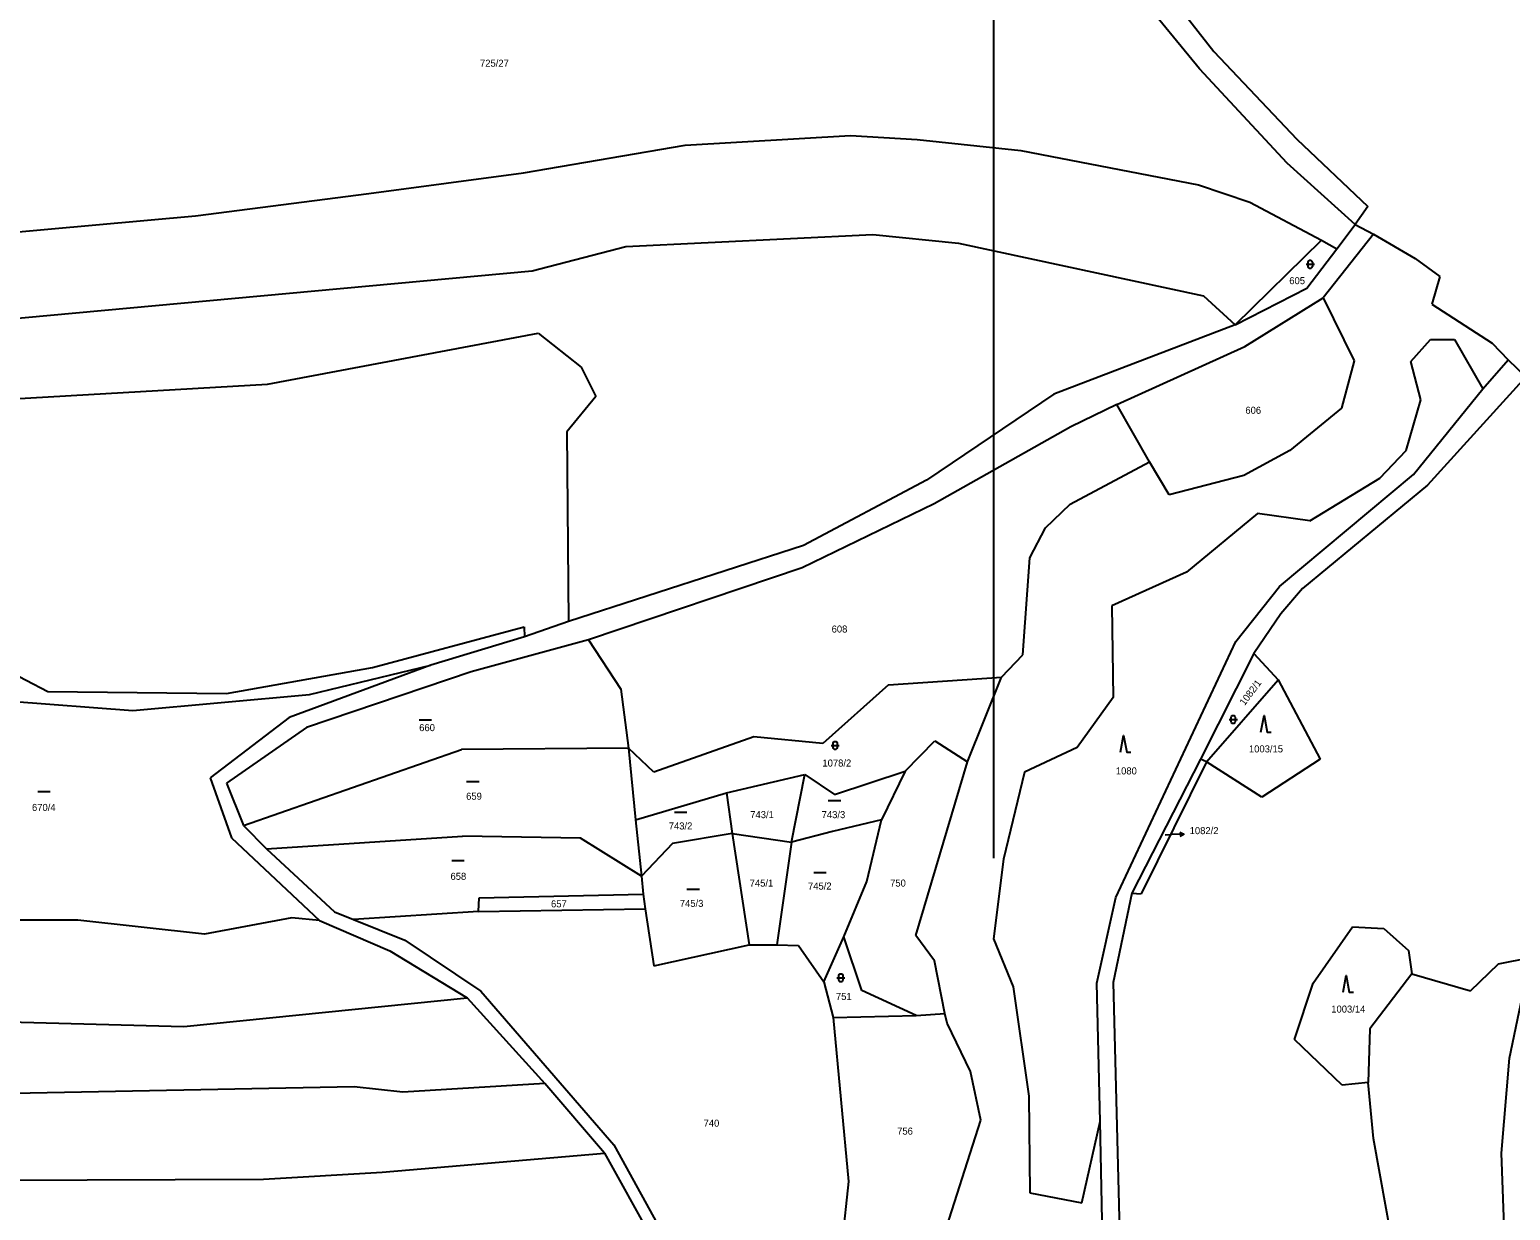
# Model space of a CAD drawing. Extents: x -799786 to -795190, y -1021716 to -1017834.
# Drawn here: x -798982.6 to -798625.3, y -1019585 to -1019300.1 of the extents above; entities that cross this region are included whole.
import ezdxf

# ---------------------------------------------------------------- set-up
doc = ezdxf.new("R2010")
doc.units = 0
for name, color, linetype in [('Default', 7, 'Continuous'), ('KLADY_ZMVM', 7, 'Continuous'), ('KN_HRANICE', 7, 'Continuous'), ('KN_KULTURY', 7, 'Continuous'), ('KN_PARCELY', 7, 'Continuous')]:
    doc.layers.add(name, color=color, linetype=linetype)

# ---------------------------------------------------------------- blocks, each defined once
blk = doc.blocks.new('308')
at = {"layer": 'Default'}
blk.add_lwpolyline([(-0.75, 0), (0, 4), (0.75, 0), (1.75, 0)], dxfattribs=at)
blk = doc.blocks.new('316')
at = {"layer": 'Default'}
for points in [[(-1, 1), (0.27, 1), (1, 1)], [(-0.5, 1.5), (-0.4, 1.79), (-0.15, 1.97), (0.16, 1.97), (0.41, 1.79), (0.51, 1.5), (0.51, 0.5), (0.41, 0.21), (0.16, 0.03), (-0.15, 0.03), (-0.4, 0.21), (-0.5, 0.5), (-0.5, 1.5)]]:
    blk.add_lwpolyline(points, dxfattribs=at)
blk = doc.blocks.new('804')
at = {"layer": 'Default'}
blk.add_line((-1.5, 0), (1.5, 0), dxfattribs=at)
blk = doc.blocks.new('10292')
at = {"layer": 'Default'}
blk.add_line((0, 3), (0, 0), dxfattribs=at)
blk.add_lwpolyline([(-0.5, 2), (0, 3), (0.5, 2)], dxfattribs=at)

msp = doc.modelspace()

# ---------------------------------------------------------------- linework, layer by layer
at = {"layer": 'KLADY_ZMVM'}
msp.add_lwpolyline([(-798750, -1018500), (-798750, -1019000), (-798750, -1019500)], dxfattribs=at)
at = {"layer": 'KN_HRANICE'}
for p, q in [((-798712.66, -1019285.13), (-798696.86, -1019305.37)), ((-798700.33, -1019309.58), (-798717.83, -1019288.18)), ((-798696.86, -1019305.37), (-798676.85, -1019326.52)), ((-798679.17, -1019332.32), (-798700.33, -1019309.58)), ((-798824.38, -1019327.98), (-798784.49, -1019325.66)), ((-798784.49, -1019325.66), (-798768.48, -1019326.61)), ((-798768.48, -1019326.61), (-798743.43, -1019329.24)), ((-798676.85, -1019326.52), (-798659.76, -1019342.78)), ((-798863.37, -1019334.62), (-798824.38, -1019327.98)), ((-798743.43, -1019329.24), (-798700.56, -1019337.56)), ((-798662.82, -1019347.1), (-798679.17, -1019332.32)), ((-798900.7, -1019339.67), (-798863.37, -1019334.62)), ((-798700.56, -1019337.56), (-798688.21, -1019341.73)), ((-798942.54, -1019345.04), (-798900.7, -1019339.67)), ((-799021.28, -1019352.13), (-798942.54, -1019345.04)), ((-798688.21, -1019341.73), (-798670.93, -1019350.9)), ((-798659.76, -1019342.78), (-798662.82, -1019347.1)), ((-798667.24, -1019353.01), (-798662.82, -1019347.1)), ((-798662.82, -1019347.1), (-798658.39, -1019349.42)), ((-798838.7, -1019352.43), (-798779.12, -1019349.49)), ((-798779.12, -1019349.49), (-798758.47, -1019351.59)), ((-798758.47, -1019351.59), (-798699.41, -1019364.34)), ((-798691.75, -1019371.31), (-798670.93, -1019350.9)), ((-798670.93, -1019350.9), (-798667.24, -1019353.01)), ((-798658.39, -1019349.42), (-798670.51, -1019364.81)), ((-798658.39, -1019349.42), (-798648.3, -1019355.31)), ((-798861.35, -1019358.33), (-798838.7, -1019352.43)), ((-798674.41, -1019362.49), (-798667.24, -1019353.01)), ((-798648.3, -1019355.31), (-798642.4, -1019359.63)), ((-798900.6, -1019361.91), (-798861.35, -1019358.33)), ((-799007.83, -1019371.82), (-798900.6, -1019361.91)), ((-798691.75, -1019371.31), (-798674.41, -1019362.49)), ((-798642.4, -1019359.63), (-798644.3, -1019366.37)), ((-798699.41, -1019364.34), (-798691.75, -1019371.31)), ((-798689.42, -1019376.56), (-798670.51, -1019364.81)), ((-798670.51, -1019364.81), (-798663.02, -1019379.97)), ((-798644.3, -1019366.37), (-798629.75, -1019375.76)), ((-798925.2, -1019385.65), (-798859.9, -1019373.32)), ((-798859.9, -1019373.32), (-798849.47, -1019381.55)), ((-798691.75, -1019371.31), (-798735.45, -1019388.04)), ((-798720.28, -1019390.57), (-798689.42, -1019376.56)), ((-798649.35, -1019380.16), (-798644.61, -1019374.89)), ((-798644.61, -1019374.89), (-798638.81, -1019374.89)), ((-798638.81, -1019374.89), (-798631.96, -1019386.8)), ((-798629.75, -1019375.76), (-798625.85, -1019379.76)), ((-798663.02, -1019379.97), (-798666.08, -1019391.46)), ((-798646.92, -1019389.44), (-798649.35, -1019380.16)), ((-798631.96, -1019386.8), (-798625.85, -1019379.76)), ((-798625.85, -1019379.76), (-798621.64, -1019383.87)), ((-798849.47, -1019381.55), (-798845.99, -1019388.61)), ((-798621.64, -1019383.87), (-798645.34, -1019409.99)), ((-799017.43, -1019390.93), (-798925.2, -1019385.65)), ((-798735.45, -1019388.04), (-798766.21, -1019408.79)), ((-798648.72, -1019407.46), (-798631.96, -1019386.8)), ((-798845.99, -1019388.61), (-798852.95, -1019397.15)), ((-798720.28, -1019390.57), (-798731.34, -1019395.94)), ((-798712.41, -1019404.41), (-798720.28, -1019390.57)), ((-798666.08, -1019391.46), (-798678.58, -1019401.67)), ((-798650.51, -1019401.66), (-798646.92, -1019389.44)), ((-798852.95, -1019397.15), (-798852.53, -1019442.89)), ((-798731.34, -1019395.94), (-798764.32, -1019414.49)), ((-798678.58, -1019401.67), (-798689.65, -1019407.68)), ((-798656.83, -1019408.3), (-798650.51, -1019401.66)), ((-798731.57, -1019414.61), (-798712.41, -1019404.41)), ((-798707.67, -1019412.32), (-798712.41, -1019404.41)), ((-798766.21, -1019408.79), (-798795.9, -1019424.57)), ((-798689.65, -1019407.68), (-798707.67, -1019412.32)), ((-798681.05, -1019434.41), (-798648.72, -1019407.46)), ((-798673.69, -1019418.64), (-798656.83, -1019408.3)), ((-798645.34, -1019409.99), (-798675.46, -1019434.93)), ((-798764.32, -1019414.49), (-798796.21, -1019429.95)), ((-798737.47, -1019420.31), (-798731.57, -1019414.61)), ((-798686.33, -1019416.84), (-798703.49, -1019431.03)), ((-798673.69, -1019418.64), (-798686.33, -1019416.84)), ((-798741.25, -1019427.55), (-798737.47, -1019420.31)), ((-798795.9, -1019424.57), (-798852.53, -1019442.89)), ((-798796.21, -1019429.95), (-798847.69, -1019447.32)), ((-798742.93, -1019450.95), (-798741.25, -1019427.55)), ((-798703.49, -1019431.03), (-798721.51, -1019439.15)), ((-798691.58, -1019447.69), (-798681.05, -1019434.41)), ((-798675.46, -1019434.93), (-798680.73, -1019441.05)), ((-798721.51, -1019439.15), (-798721.17, -1019461.24)), ((-798680.73, -1019441.05), (-798687.26, -1019450.64)), ((-798899.85, -1019453.96), (-798863.28, -1019444.15)), ((-798863.28, -1019444.15), (-798863.18, -1019446.58)), ((-798852.53, -1019442.89), (-798863.18, -1019446.58)), ((-798863.18, -1019446.58), (-798885.73, -1019453.43)), ((-798847.69, -1019447.32), (-798876.03, -1019455.01)), ((-798847.69, -1019447.32), (-798839.89, -1019459.23)), ((-798720.54, -1019509.52), (-798691.58, -1019447.69)), ((-798748.1, -1019456.33), (-798742.93, -1019450.95)), ((-798687.26, -1019450.64), (-798700.1, -1019476.1)), ((-798687.26, -1019450.64), (-798681.36, -1019456.97)), ((-798988.61, -1019454.34), (-798978.18, -1019459.77)), ((-798935.07, -1019460.27), (-798899.85, -1019453.96)), ((-798885.73, -1019453.43), (-798919.97, -1019466.08)), ((-798876.03, -1019455.01), (-798915.74, -1019468.48)), ((-798915.02, -1019460.49), (-798885.73, -1019453.43)), ((-798839.89, -1019459.23), (-798838.1, -1019473.46)), ((-798775.39, -1019458.21), (-798791.19, -1019472.31)), ((-798775.39, -1019458.21), (-798748.1, -1019456.33)), ((-798756.31, -1019476.73), (-798748.1, -1019456.33)), ((-798698.62, -1019476.74), (-798681.36, -1019456.97)), ((-798681.36, -1019456.97), (-798671.22, -1019476.1)), ((-798987.14, -1019462.09), (-798957.62, -1019464.38)), ((-798978.18, -1019459.77), (-798935.07, -1019460.27)), ((-798957.62, -1019464.38), (-798915.02, -1019460.49)), ((-798721.17, -1019461.24), (-798729.81, -1019473.26)), ((-798919.97, -1019466.08), (-798939.03, -1019480.6)), ((-798915.74, -1019468.48), (-798935.03, -1019481.86)), ((-798930.92, -1019492.09), (-798878.34, -1019473.75)), ((-798838.1, -1019473.46), (-798878.34, -1019473.75)), ((-798838.1, -1019473.46), (-798836.41, -1019490.72)), ((-798831.96, -1019479.28), (-798838.1, -1019473.46)), ((-798807.84, -1019470.72), (-798831.96, -1019479.28)), ((-798791.19, -1019472.31), (-798807.84, -1019470.72)), ((-798771.38, -1019479.04), (-798764.22, -1019471.67)), ((-798764.22, -1019471.67), (-798756.31, -1019476.73)), ((-798729.81, -1019473.26), (-798742.56, -1019479.27)), ((-798768.76, -1019518.63), (-798756.31, -1019476.73)), ((-798700.1, -1019476.1), (-798716.64, -1019508.47)), ((-798698.62, -1019476.74), (-798714.43, -1019508.57)), ((-798698.62, -1019476.74), (-798700.1, -1019476.1)), ((-798685.34, -1019485.27), (-798698.62, -1019476.74)), ((-798671.22, -1019476.1), (-798685.34, -1019485.27)), ((-798939.03, -1019480.6), (-798933.88, -1019495.07)), ((-798814.48, -1019484.22), (-798795.51, -1019479.79)), ((-798798.78, -1019496.11), (-798795.51, -1019479.79)), ((-798795.51, -1019479.79), (-798788.35, -1019484.62)), ((-798788.35, -1019484.62), (-798771.38, -1019479.04)), ((-798771.38, -1019479.04), (-798777.07, -1019490.74)), ((-798742.56, -1019479.27), (-798747.62, -1019500.24)), ((-798935.03, -1019481.86), (-798930.92, -1019492.09)), ((-798836.41, -1019490.72), (-798814.48, -1019484.22)), ((-798814.48, -1019484.22), (-798813.11, -1019494.02)), ((-798836.41, -1019490.72), (-798834.94, -1019504.32)), ((-798777.07, -1019490.74), (-798788.88, -1019493.58)), ((-798780.55, -1019505.6), (-798777.07, -1019490.74)), ((-798933.88, -1019495.07), (-798912.6, -1019515.04)), ((-798930.92, -1019492.09), (-798925.44, -1019497.78)), ((-798925.44, -1019497.78), (-798878.13, -1019494.72)), ((-798849.67, -1019495.15), (-798878.13, -1019494.72)), ((-798834.94, -1019504.32), (-798849.67, -1019495.15)), ((-798813.11, -1019494.02), (-798827.44, -1019496.45)), ((-798813.11, -1019494.02), (-798809, -1019520.89)), ((-798813.11, -1019494.02), (-798798.78, -1019496.11)), ((-798788.88, -1019493.58), (-798798.78, -1019496.11)), ((-798925.44, -1019497.78), (-798909.01, -1019512.93)), ((-798827.44, -1019496.45), (-798834.94, -1019504.32)), ((-798798.78, -1019496.11), (-798802.26, -1019520.89)), ((-798747.62, -1019500.24), (-798750, -1019519.48)), ((-798834.94, -1019504.32), (-798834.52, -1019508.65)), ((-798786.14, -1019518.95), (-798780.55, -1019505.6)), ((-798874.14, -1019509.59), (-798834.52, -1019508.65)), ((-798834.52, -1019508.65), (-798834.1, -1019512.23)), ((-798725.07, -1019530.18), (-798720.54, -1019509.52)), ((-798716.64, -1019508.47), (-798721.17, -1019529.97)), ((-798716.64, -1019508.47), (-798714.43, -1019508.57)), ((-798909.01, -1019512.93), (-798904.38, -1019514.83)), ((-798874.24, -1019512.86), (-798904.38, -1019514.83)), ((-798874.24, -1019512.86), (-798874.14, -1019509.59)), ((-798874.24, -1019512.86), (-798834.1, -1019512.23)), ((-798834.1, -1019512.23), (-798831.99, -1019525.93)), ((-798970.92, -1019514.98), (-799009.92, -1019514.98)), ((-798940.36, -1019518.35), (-798970.92, -1019514.98)), ((-798919.29, -1019514.35), (-798940.36, -1019518.35)), ((-798912.6, -1019515.04), (-798919.29, -1019514.35)), ((-798912.6, -1019515.04), (-798895.63, -1019522.31)), ((-798904.38, -1019514.83), (-798892.05, -1019519.78)), ((-798672.88, -1019530.17), (-798663.4, -1019516.52)), ((-798663.4, -1019516.52), (-798655.86, -1019516.94)), ((-798892.05, -1019519.78), (-798873.74, -1019532.08)), ((-798790.99, -1019529.81), (-798786.14, -1019518.95)), ((-798781.82, -1019531.92), (-798786.14, -1019518.95)), ((-798764.23, -1019524.75), (-798768.76, -1019518.63)), ((-798750, -1019519.48), (-798745.29, -1019531.06)), ((-798655.86, -1019516.94), (-798649.91, -1019522.27)), ((-798895.63, -1019522.31), (-798877, -1019533.66)), ((-798831.99, -1019525.93), (-798809, -1019520.89)), ((-798809, -1019520.89), (-798802.26, -1019520.89)), ((-798802.26, -1019520.89), (-798797.1, -1019521.1)), ((-798797.1, -1019521.1), (-798790.99, -1019529.81)), ((-798649.91, -1019522.27), (-798649.12, -1019527.91)), ((-798761.81, -1019537.48), (-798764.23, -1019524.75)), ((-798634.99, -1019532.01), (-798628.24, -1019525.47)), ((-798628.24, -1019525.47), (-798620.45, -1019523.99)), ((-798625.52, -1019548.27), (-798620.45, -1019523.99)), ((-798790.99, -1019529.81), (-798788.67, -1019538.45)), ((-798724.33, -1019563.53), (-798725.07, -1019530.18)), ((-798721.17, -1019529.97), (-798719.63, -1019589.9)), ((-798677.41, -1019543.72), (-798672.88, -1019530.17)), ((-798649.12, -1019527.91), (-798659.24, -1019541.19)), ((-798649.12, -1019527.91), (-798634.99, -1019532.01)), ((-798945.32, -1019540.6), (-798877, -1019533.66)), ((-798877, -1019533.66), (-798858.25, -1019554.32)), ((-798873.74, -1019532.08), (-798841.6, -1019569.19)), ((-798768.65, -1019537.93), (-798781.82, -1019531.92)), ((-798745.29, -1019531.06), (-798741.5, -1019557.42)), ((-798788.67, -1019538.45), (-798768.65, -1019537.93)), ((-798768.65, -1019537.93), (-798761.81, -1019537.48)), ((-798761.18, -1019539.8), (-798761.81, -1019537.48)), ((-798996.61, -1019539.23), (-798945.32, -1019540.6)), ((-798788.67, -1019538.45), (-798784.99, -1019577.96)), ((-798755.59, -1019551.5), (-798761.18, -1019539.8)), ((-798659.24, -1019541.19), (-798659.64, -1019554.1)), ((-798665.96, -1019554.77), (-798677.41, -1019543.72)), ((-798627.51, -1019571.18), (-798625.52, -1019548.27)), ((-798753.06, -1019563.2), (-798755.59, -1019551.5)), ((-798904.22, -1019555.15), (-799000.93, -1019557.04)), ((-798892.52, -1019556.41), (-798904.22, -1019555.15)), ((-798858.25, -1019554.32), (-798892.52, -1019556.41)), ((-798843.91, -1019571.19), (-798858.25, -1019554.32)), ((-798659.64, -1019554.1), (-798665.96, -1019554.77)), ((-798658.38, -1019567.59), (-798659.64, -1019554.1)), ((-798741.5, -1019557.42), (-798741.29, -1019580.72)), ((-798763.39, -1019595.46), (-798753.06, -1019563.2)), ((-798728.75, -1019583.14), (-798724.33, -1019563.53)), ((-798723.85, -1019587.37), (-798724.33, -1019563.53)), ((-798841.6, -1019569.19), (-798827.09, -1019595.48)), ((-798653.74, -1019592.96), (-798658.38, -1019567.59)), ((-798897.47, -1019575.71), (-798843.91, -1019571.19)), ((-798843.91, -1019571.19), (-798832.55, -1019591.58)), ((-798626.43, -1019600.01), (-798627.51, -1019571.18)), ((-798926.11, -1019577.44), (-798897.47, -1019575.71)), ((-798990.03, -1019577.71), (-798926.11, -1019577.44)), ((-798784.99, -1019577.96), (-798786.52, -1019592.32)), ((-798741.29, -1019580.72), (-798728.75, -1019583.14))]:
    msp.add_line(p, q, dxfattribs=at)
at = {"layer": 'KN_PARCELY'}
msp.add_line((-798708.64, -1019494.38), (-798707.1, -1019494.32), dxfattribs=at)

# ---------------------------------------------------------------- block references
at = {"layer": 'KN_KULTURY'}
for name, p in [('316', (-798673.61, -1019357.72)), ('804', (-798887.08, -1019466.65)), ('316', (-798692.21, -1019467.54)), ('308', (-798684.77, -1019469.61)), ('316', (-798788.23, -1019473.78)), ('308', (-798718.65, -1019474.41)), ('804', (-798979.06, -1019483.92)), ('804', (-798875.62, -1019481.47)), ('804', (-798788.39, -1019486.1)), ('804', (-798825.47, -1019488.9)), ('804', (-798879.2, -1019500.54)), ('804', (-798791.88, -1019503.46)), ('804', (-798822.48, -1019507.45)), ('316', (-798786.86, -1019529.84)), ('308', (-798664.97, -1019532.31))]:
    msp.add_blockref(name, p, dxfattribs=at)
at = {"layer": 'KN_PARCELY', "rotation": -87.73045600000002}
msp.add_blockref('10292', (-798707.1, -1019494.32), dxfattribs=at)

# ---------------------------------------------------------------- texts
at = {"layer": 'KN_PARCELY'}
for s, height, p in [('725/27', 1.7, (-798873.9, -1019309.05)), ('605', 1.7, (-798678.68, -1019361.51)), ('606', 1.7, (-798689.27, -1019392.78)), ('608', 1.7, (-798789.08, -1019445.56)), ('660', 1.7, (-798888.57, -1019469.35)), ('1003/15', 1.7, (-798688.41, -1019474.48)), ('1078/2', 1.7, (-798791.3, -1019477.89)), ('1080', 1.7, (-798720.51, -1019479.79)), ('659', 1.7, (-798877.25, -1019485.9)), ('670/4', 1.7, (-798981.97, -1019488.6)), ('743/2', 1.7, (-798828.37, -1019493.07)), ('743/1', 1.7, (-798808.71, -1019490.34)), ('743/3', 1.7, (-798791.48, -1019490.34)), ('1082/2', 0.1, (-798708.62, -1019494.38)), ('1082/2', 1.7, (-798702.71, -1019494.2)), ('658', 1.7, (-798881.02, -1019505.22)), ('745/1', 1.7, (-798808.85, -1019506.85)), ('745/2', 1.7, (-798794.78, -1019507.57)), ('750', 1.7, (-798774.97, -1019506.85)), ('657', 1.7, (-798856.77, -1019511.87)), ('745/3', 1.7, (-798825.7, -1019511.75)), ('751', 1.7, (-798788.04, -1019534.2)), ('1003/14', 1.7, (-798668.55, -1019537.25)), ('740', 1.7, (-798819.97, -1019564.78)), ('756', 1.7, (-798773.27, -1019566.69))]:
    msp.add_text(s, height=height, dxfattribs=at).set_placement(p)
msp.add_text('1082/1', height=1.7, rotation=53.285, dxfattribs=at).set_placement((-798689.45, -1019463.31))

doc.saveas('drawing.dxf')
